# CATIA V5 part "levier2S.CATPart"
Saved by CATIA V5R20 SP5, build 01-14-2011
Part number: levier2S
Publications: "Plan.1", "Point.2", "Point.1", "Droite.1"
Bounding box of the stored display mesh (mm): x 0 to 0, y -90 to 200, z 0 to 1250
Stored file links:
  U:\think motion\fin\levier2S.CATPart
  U:\think motion\fin\squelette.CATProduct
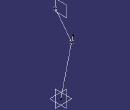
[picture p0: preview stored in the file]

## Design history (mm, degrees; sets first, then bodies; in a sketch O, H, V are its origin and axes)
External parameters (linked from other documents)
  `External.eloignement axe` = 60 mm
  `External.ecartement axe` = 50 mm
Set1
  Plane1: linked copy from another document
  Point1: linked copy from another document
  Line1: linked copy from another document
Set2
  Point2: type OnCurve, Support Line1, Length 100 {= `External.ecartement axe` *2}
  Line2: type PtPt, FirstPoint Point1, SecondPoint Point2
Body1 (main body)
